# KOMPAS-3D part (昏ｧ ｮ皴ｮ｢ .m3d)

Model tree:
1. Эскиз:1
2. Операция выдавливания:1
     Расстояние 1 = 8
3. Эскиз:2
4. Вырезать элемент выдавливания:1
     Расстояние 1 = 10
5. Эскиз:3
6. Вырезать элемент выдавливания:2
     Расстояние 1 = 10
7. Эскиз:5
8. Эскиз:6
9. Вырезать элемент выдавливания:5
     Расстояние 1 = 10

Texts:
  Пиломатериал сосна  ГОСТ 8486-86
